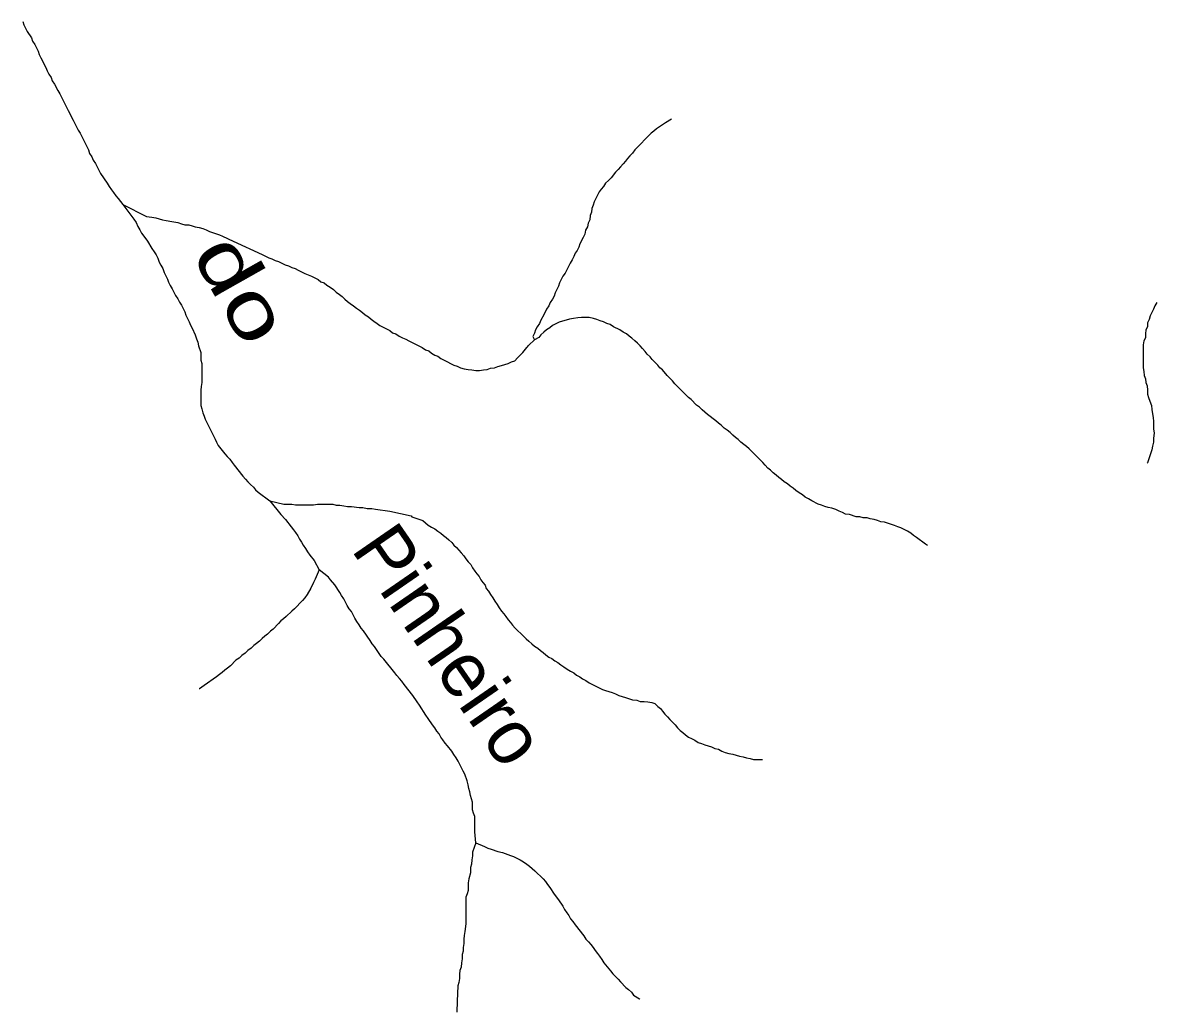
# Model space of a CAD drawing. Extents: x 652.3 to 678, y 7316.9 to 7344.9.
# Drawn here: x 668.578 to 670.225, y 7341.639 to 7343.077 of the extents above; entities that cross this region are included whole.
import ezdxf
from ezdxf.enums import TextEntityAlignment as Align

# ---------------------------------------------------------------- set-up
doc = ezdxf.new("R2010")
doc.units = 0
doc.header["$LTSCALE"] = 0.032
doc.layers.add('61', color=7, linetype='Continuous')
doc.layers.add('7', color=7, linetype='Continuous', lineweight=25)

msp = doc.modelspace()

# ---------------------------------------------------------------- linework, layer by layer
at = {"layer": '7'}
for points in [[(668.5783, 7343.0784), (668.5799, 7343.0737), (668.5823, 7343.0689), (668.5847, 7343.0641), (668.591, 7343.0546), (668.5926, 7343.0498), (668.5958, 7343.045), (668.6006, 7343.0355), (668.6022, 7343.0307), (668.6046, 7343.0259), (668.6117, 7343.0116), (668.6141, 7343.0068), (668.6165, 7343.0021), (668.6197, 7342.9973), (668.6213, 7342.9925), (668.6245, 7342.9877), (668.6292, 7342.9782), (668.6324, 7342.9734), (668.6348, 7342.9686), (668.642, 7342.9543), (668.6443, 7342.9495), (668.6515, 7342.9352), (668.6539, 7342.9304), (668.6587, 7342.9209), (668.6618, 7342.9161), (668.6642, 7342.9113), (668.6714, 7342.897), (668.6738, 7342.8922), (668.6754, 7342.8867), (668.6786, 7342.8819), (668.6809, 7342.8771), (668.6841, 7342.8724), (668.6889, 7342.8628), (668.6913, 7342.858), (668.7008, 7342.8437), (668.704, 7342.8389), (668.7072, 7342.8342), (668.7104, 7342.8302), (668.7136, 7342.8254), (668.7168, 7342.8214), (668.7239, 7342.8127)], [(669.5204, 7342.9368), (669.5116, 7342.9312), (669.5029, 7342.9257), (669.4989, 7342.9225), (669.4949, 7342.9193), (669.491, 7342.9161), (669.4671, 7342.8922), (669.4639, 7342.8875), (669.4599, 7342.8835), (669.4567, 7342.8795), (669.4536, 7342.8755), (669.4504, 7342.8716), (669.4464, 7342.8676), (669.4432, 7342.8636), (669.4392, 7342.8596), (669.4329, 7342.8517), (669.4289, 7342.8477), (669.4249, 7342.8437), (669.4217, 7342.8389), (669.4185, 7342.835), (669.4154, 7342.831), (669.413, 7342.8262), (669.4082, 7342.8167), (669.4066, 7342.8119), (669.405, 7342.8071), (669.4042, 7342.8015), (669.4026, 7342.7968), (669.4018, 7342.7904), (669.3995, 7342.7856), (669.3987, 7342.7801), (669.3955, 7342.7753), (669.3947, 7342.7697), (669.3923, 7342.7649), (669.3875, 7342.7554), (669.3859, 7342.7506), (669.3835, 7342.7458), (669.3804, 7342.7419), (669.3788, 7342.7371), (669.3764, 7342.7323), (669.3732, 7342.7275), (669.3708, 7342.7228), (669.3684, 7342.718), (669.366, 7342.7132), (669.3628, 7342.7084), (669.3605, 7342.7037), (669.3581, 7342.6989), (669.3565, 7342.6941), (669.3517, 7342.6846), (669.3501, 7342.6798), (669.3477, 7342.675), (669.3445, 7342.6703), (669.3422, 7342.6655), (669.339, 7342.6607), (669.335, 7342.6527), (669.331, 7342.6448), (669.3286, 7342.64), (669.3255, 7342.6352), (669.3231, 7342.6305), (669.3215, 7342.6257), (669.3191, 7342.6209), (669.3215, 7342.6161)], [(668.7239, 7342.8127), (668.7239, 7342.8127), (668.7581, 7342.7952)], [(668.7239, 7342.8127), (668.7239, 7342.8127), (668.7398, 7342.7912), (668.7398, 7342.7912)], [(668.7581, 7342.7952), (668.7661, 7342.7944), (668.7717, 7342.7936), (668.7812, 7342.7904), (668.7868, 7342.7896), (668.7947, 7342.788), (668.8035, 7342.7864), (668.8091, 7342.7848), (668.8138, 7342.7832), (668.8194, 7342.7832), (668.8242, 7342.7816), (668.8289, 7342.7801), (668.8345, 7342.7793), (668.8401, 7342.7777), (668.8449, 7342.7761), (668.8496, 7342.7737), (668.864, 7342.7689), (668.8687, 7342.7665), (668.8838, 7342.7594)], [(668.7398, 7342.7912), (668.743, 7342.7864), (668.7454, 7342.7809), (668.7486, 7342.7761), (668.751, 7342.7713), (668.7541, 7342.7665), (668.7597, 7342.7594), (668.7661, 7342.749), (668.7693, 7342.7442), (668.7724, 7342.7395), (668.7748, 7342.7347), (668.7764, 7342.7291), (668.7788, 7342.7244), (668.782, 7342.7196), (668.7836, 7342.714), (668.786, 7342.7092), (668.7884, 7342.7045), (668.79, 7342.6997), (668.7923, 7342.6949), (668.7955, 7342.6901), (668.8003, 7342.6806), (668.8035, 7342.6758), (668.8059, 7342.671), (668.8091, 7342.6663), (668.8138, 7342.6567), (668.8154, 7342.6519), (668.8202, 7342.6424), (668.8218, 7342.6376), (668.8242, 7342.6329), (668.8289, 7342.6233), (668.8305, 7342.6177), (668.8329, 7342.613), (668.8337, 7342.6074), (668.8369, 7342.5978), (668.8369, 7342.5867), (668.8385, 7342.5819), (668.8385, 7342.5541), (668.8377, 7342.5485), (668.8369, 7342.5429), (668.8369, 7342.5207), (668.8385, 7342.5159), (668.8401, 7342.5103), (668.8417, 7342.5055), (668.8433, 7342.5008), (668.848, 7342.4912), (668.8504, 7342.4864), (668.8576, 7342.4721), (668.86, 7342.4673), (668.8624, 7342.4626), (668.8719, 7342.4506), (668.8751, 7342.4467), (668.8791, 7342.4427), (668.8823, 7342.4379), (668.8854, 7342.4339), (668.8982, 7342.418), (668.9021, 7342.414), (668.9053, 7342.4101), (668.9093, 7342.4061), (668.9133, 7342.4021), (668.9165, 7342.3981), (668.9204, 7342.3949), (668.9372, 7342.3822)], [(668.8838, 7342.7594), (668.926, 7342.7403), (668.9356, 7342.7355), (668.9403, 7342.7339), (668.9451, 7342.7315), (668.9499, 7342.7299), (668.9547, 7342.7275), (668.9594, 7342.7252), (668.9642, 7342.7236), (668.969, 7342.7212), (668.9738, 7342.7196), (668.9785, 7342.7172), (668.9833, 7342.7148), (668.9881, 7342.7124), (668.9929, 7342.7108), (668.9976, 7342.7084), (669.0024, 7342.7061), (669.0072, 7342.7037), (669.0112, 7342.7005), (669.0159, 7342.6989), (669.0199, 7342.6957), (669.0247, 7342.6925), (669.0295, 7342.6893), (669.0334, 7342.6854), (669.0382, 7342.6822), (669.0422, 7342.679), (669.0462, 7342.675), (669.0501, 7342.6718), (669.0541, 7342.6687), (669.0589, 7342.6655), (669.0629, 7342.6623), (669.0676, 7342.6591), (669.0716, 7342.6559), (669.0756, 7342.6527), (669.0804, 7342.6496), (669.0844, 7342.6464), (669.0883, 7342.6432), (669.0931, 7342.64), (669.0971, 7342.6368), (669.1019, 7342.6344), (669.1066, 7342.6321), (669.1114, 7342.6297), (669.1154, 7342.6265), (669.1202, 7342.6249), (669.1249, 7342.6217), (669.1297, 7342.6193), (669.1345, 7342.6169), (669.1393, 7342.6146), (669.144, 7342.6122), (669.1488, 7342.6098), (669.1536, 7342.6074), (669.1584, 7342.605), (669.1631, 7342.6018), (669.1679, 7342.6002), (669.1719, 7342.597), (669.1767, 7342.5939), (669.1814, 7342.5923), (669.1854, 7342.5891), (669.1902, 7342.5867), (669.195, 7342.5843), (669.1997, 7342.5819), (669.2045, 7342.5795), (669.2093, 7342.578), (669.2141, 7342.5756), (669.2196, 7342.574), (669.2252, 7342.5732), (669.2308, 7342.5724), (669.2363, 7342.5716), (669.2419, 7342.5716), (669.2475, 7342.5724), (669.253, 7342.5732), (669.2578, 7342.5748), (669.2634, 7342.5756), (669.2682, 7342.5772), (669.2737, 7342.5787), (669.2785, 7342.5803), (669.2833, 7342.5819), (669.2881, 7342.5843), (669.2928, 7342.5859), (669.2968, 7342.5899), (669.3048, 7342.5978), (669.3103, 7342.605), (669.3114, 7342.6062), (669.3125, 7342.6074), (669.3135, 7342.6086), (669.3215, 7342.6161)], [(670.2254, 7342.6703), (670.2222, 7342.6655), (670.2206, 7342.6607), (670.2158, 7342.6512), (670.2142, 7342.6456), (670.2118, 7342.6408), (670.2118, 7342.6352), (670.2095, 7342.6305), (670.2087, 7342.6249), (670.2087, 7342.6193), (670.2063, 7342.6146), (670.2055, 7342.609), (670.2055, 7342.5756), (670.2063, 7342.57), (670.2071, 7342.5644), (670.2087, 7342.5596), (670.2095, 7342.5541), (670.2111, 7342.5493), (670.2118, 7342.5429), (670.2118, 7342.5374), (670.2134, 7342.5326), (670.215, 7342.527), (670.2174, 7342.5207), (670.2182, 7342.5151), (670.219, 7342.5087), (670.2198, 7342.5032), (670.2206, 7342.4976), (670.2206, 7342.4864), (670.2214, 7342.4809), (670.2206, 7342.4729), (670.2206, 7342.4673), (670.219, 7342.4618), (670.2182, 7342.4562), (670.2126, 7342.4403), (670.2116, 7342.4373), (670.2115, 7342.4369)], [(669.3724, 7342.6464), (669.3676, 7342.6448), (669.3621, 7342.6432), (669.3573, 7342.6416), (669.3477, 7342.6368), (669.3438, 7342.6336), (669.339, 7342.6305), (669.335, 7342.6273), (669.331, 7342.6233), (669.3281, 7342.6197), (669.3215, 7342.6161)], [(669.8925, 7342.3173), (669.8922, 7342.3175), (669.8896, 7342.3194), (669.8761, 7342.3289), (669.8721, 7342.3321), (669.8681, 7342.3353), (669.8633, 7342.3384), (669.8538, 7342.3432), (669.849, 7342.3448), (669.8442, 7342.3464), (669.8299, 7342.3512), (669.8243, 7342.352), (669.8196, 7342.3536), (669.8148, 7342.3552), (669.8092, 7342.356), (669.8045, 7342.3575), (669.7989, 7342.3575), (669.7941, 7342.3591), (669.7885, 7342.3591), (669.779, 7342.3623), (669.7734, 7342.3631), (669.7687, 7342.3655), (669.7639, 7342.3671), (669.7591, 7342.3695), (669.7535, 7342.3719), (669.748, 7342.3727), (669.7432, 7342.3743), (669.7384, 7342.3758), (669.7336, 7342.3774), (669.7241, 7342.3822), (669.7193, 7342.3854), (669.7145, 7342.3878), (669.7106, 7342.391), (669.7058, 7342.3941), (669.701, 7342.3973), (669.697, 7342.4005), (669.6931, 7342.4037), (669.6891, 7342.4069), (669.6843, 7342.4101), (669.6803, 7342.4132), (669.6764, 7342.4164), (669.6724, 7342.4196), (669.6684, 7342.4228), (669.6644, 7342.4268), (669.6604, 7342.43), (669.6565, 7342.4339), (669.6533, 7342.4379), (669.6334, 7342.4578), (669.6294, 7342.461), (669.6254, 7342.4642), (669.6214, 7342.4673), (669.6175, 7342.4713), (669.6135, 7342.4745), (669.6095, 7342.4777), (669.6055, 7342.4817), (669.6016, 7342.4849), (669.5968, 7342.488), (669.5928, 7342.492), (669.5888, 7342.4952), (669.5848, 7342.4984), (669.5809, 7342.5016), (669.5769, 7342.5047), (669.5729, 7342.5079), (669.5689, 7342.5111), (669.565, 7342.5143), (669.561, 7342.5183), (669.557, 7342.5215), (669.549, 7342.5294), (669.5451, 7342.5326), (669.5291, 7342.5485), (669.5252, 7342.5525), (669.522, 7342.5565), (669.514, 7342.5644), (669.5077, 7342.5724), (669.5037, 7342.5756), (669.5005, 7342.5795), (669.4925, 7342.5875), (669.4894, 7342.5915), (669.4854, 7342.5955), (669.4822, 7342.5994), (669.4782, 7342.6034), (669.475, 7342.6074), (669.4711, 7342.6114), (669.4671, 7342.6146), (669.4631, 7342.6185), (669.4591, 7342.6217), (669.4551, 7342.6249), (669.4504, 7342.6273), (669.4456, 7342.6305), (669.4361, 7342.6352), (669.4313, 7342.6384), (669.4265, 7342.64), (669.4217, 7342.6424), (669.417, 7342.644), (669.4122, 7342.6456), (669.4074, 7342.6472), (669.401, 7342.6488), (669.3899, 7342.6488), (669.3843, 7342.648), (669.378, 7342.6472), (669.3724, 7342.6464)], [(668.9372, 7342.3822), (668.9578, 7342.3774), (668.969, 7342.3774), (668.9746, 7342.3766), (669.0008, 7342.3766), (669.0064, 7342.3774), (669.0287, 7342.3774), (669.0334, 7342.3758), (669.039, 7342.3758), (669.0446, 7342.375), (669.0501, 7342.3743), (669.0557, 7342.3743), (669.0669, 7342.3727), (669.0724, 7342.3727), (669.0788, 7342.3711), (669.0852, 7342.3711), (669.0907, 7342.3703), (669.1114, 7342.3671)], [(668.9372, 7342.3822), (668.9531, 7342.3623), (668.9602, 7342.3552), (668.9682, 7342.3448), (668.9714, 7342.34), (668.9746, 7342.3361), (668.9777, 7342.3313), (668.9801, 7342.3265), (668.9833, 7342.3225), (668.9857, 7342.3178), (668.9889, 7342.313), (668.9921, 7342.3082), (668.9952, 7342.3034), (669.0016, 7342.2955), (669.0088, 7342.282)], [(669.1114, 7342.3671), (669.1424, 7342.3607), (669.1432, 7342.3591), (669.1592, 7342.3536), (669.1631, 7342.3504), (669.1671, 7342.3472), (669.1719, 7342.344), (669.1767, 7342.3416), (669.1814, 7342.3384), (669.1854, 7342.3353), (669.1894, 7342.3321), (669.1934, 7342.3289), (669.1973, 7342.3257), (669.2013, 7342.3217), (669.2045, 7342.3178), (669.2085, 7342.3146), (669.2117, 7342.3106), (669.2149, 7342.3066), (669.2188, 7342.3026), (669.222, 7342.2979), (669.2252, 7342.2939), (669.2292, 7342.2899), (669.2316, 7342.2851), (669.2347, 7342.2804), (669.2379, 7342.2764), (669.2411, 7342.2724), (669.2435, 7342.2676), (669.2467, 7342.2637), (669.2499, 7342.2597), (669.2515, 7342.2549), (669.2546, 7342.2509), (669.2578, 7342.2461), (669.261, 7342.2414), (669.2642, 7342.2366), (669.2674, 7342.2318), (669.2705, 7342.2271), (669.2737, 7342.2223), (669.2769, 7342.2183), (669.2801, 7342.2143), (669.2833, 7342.2095), (669.2865, 7342.2056), (669.2896, 7342.2016), (669.2936, 7342.1976), (669.2976, 7342.1936), (669.3016, 7342.1897), (669.3056, 7342.1857), (669.3095, 7342.1817), (669.3135, 7342.1785), (669.3175, 7342.1745), (669.3215, 7342.1714), (669.3262, 7342.1682), (669.3302, 7342.165), (669.3342, 7342.1618), (669.3382, 7342.1586), (669.3422, 7342.1554), (669.3469, 7342.1531), (669.3509, 7342.1499), (669.3557, 7342.1475), (669.3597, 7342.1443), (669.3644, 7342.1411), (669.3692, 7342.1379), (669.374, 7342.1348), (669.3788, 7342.1324), (669.3827, 7342.1292), (669.3875, 7342.1268), (669.3915, 7342.1236), (669.3963, 7342.1212), (669.401, 7342.118), (669.4058, 7342.1157), (669.4106, 7342.1133), (669.4154, 7342.1109), (669.4201, 7342.1085), (669.4249, 7342.1069), (669.4297, 7342.1053), (669.4345, 7342.1037), (669.4392, 7342.1021), (669.444, 7342.0997), (669.4488, 7342.0982), (669.4536, 7342.0966), (669.4583, 7342.095), (669.4639, 7342.0934), (669.4703, 7342.0926), (669.475, 7342.091), (669.4806, 7342.091), (669.4862, 7342.0902), (669.4918, 7342.0894), (669.4965, 7342.0878), (669.5005, 7342.0838), (669.5045, 7342.0806), (669.5077, 7342.0767), (669.5108, 7342.0727), (669.5148, 7342.0687), (669.518, 7342.0647), (669.522, 7342.0608), (669.526, 7342.0568), (669.5291, 7342.0528), (669.5331, 7342.0488), (669.5371, 7342.0456), (669.5411, 7342.0425), (669.5451, 7342.0393), (669.5498, 7342.0369)], [(669.0088, 7342.282), (669.0032, 7342.2684), (669.0008, 7342.2637), (668.9968, 7342.2557), (668.9913, 7342.2461), (668.9881, 7342.2414), (668.9849, 7342.2374), (668.973, 7342.2255), (668.969, 7342.2223), (668.961, 7342.2143), (668.957, 7342.2111), (668.9531, 7342.208), (668.9499, 7342.204), (668.9419, 7342.196), (668.938, 7342.1928), (668.934, 7342.1889), (668.93, 7342.1857), (668.926, 7342.1825), (668.922, 7342.1785), (668.9181, 7342.1753), (668.9141, 7342.1721), (668.9101, 7342.1682), (668.9053, 7342.165), (668.9014, 7342.161), (668.8966, 7342.1578), (668.8926, 7342.1538), (668.8878, 7342.1507), (668.8799, 7342.1427), (668.8759, 7342.1395), (668.8719, 7342.1363), (668.8679, 7342.1332), (668.864, 7342.13), (668.86, 7342.1268), (668.8417, 7342.1141), (668.8351, 7342.1095), (668.8348, 7342.1093)], [(669.2363, 7341.8857), (669.2347, 7341.9016), (669.2347, 7341.9239), (669.2332, 7341.9287), (669.2316, 7341.9334), (669.2316, 7341.9446), (669.2284, 7341.9541), (669.2276, 7341.9597), (669.226, 7341.9645), (669.2252, 7341.97), (669.2236, 7341.9756), (669.2204, 7341.9852), (669.218, 7341.9899), (669.2156, 7341.9947), (669.2109, 7342.0043), (669.2077, 7342.009), (669.2045, 7342.0138), (669.2013, 7342.0186), (669.195, 7342.0265), (669.1918, 7342.0305), (669.1886, 7342.0353), (669.1854, 7342.0393), (669.183, 7342.044), (669.1798, 7342.048), (669.1767, 7342.0528), (669.1735, 7342.0568), (669.1671, 7342.0663), (669.1639, 7342.0711), (669.1544, 7342.0854), (669.1512, 7342.0902), (669.1448, 7342.0997), (669.1321, 7342.1157), (669.1289, 7342.1204), (669.1257, 7342.1244), (669.1218, 7342.1284), (669.1186, 7342.1324), (669.1027, 7342.1523), (669.0987, 7342.1562), (669.0891, 7342.1706), (669.086, 7342.1745), (669.0828, 7342.1793), (669.0732, 7342.1936), (669.07, 7342.1976), (669.0669, 7342.2024), (669.0637, 7342.2072), (669.0605, 7342.2119), (669.0557, 7342.2215), (669.0525, 7342.2255), (669.0493, 7342.2302), (669.0446, 7342.2398), (669.0414, 7342.2446), (669.039, 7342.2493), (669.0318, 7342.2605), (669.0255, 7342.2676), (669.0223, 7342.2716), (669.0088, 7342.282)], [(669.5498, 7342.0369), (669.5546, 7342.0345), (669.5594, 7342.0313), (669.5642, 7342.0297), (669.5689, 7342.0281), (669.5737, 7342.0265), (669.5785, 7342.0249), (669.5833, 7342.0226), (669.5888, 7342.0218), (669.5936, 7342.0186), (669.5984, 7342.017), (669.6039, 7342.0154), (669.6095, 7342.0146), (669.6143, 7342.013), (669.6191, 7342.0114), (669.6246, 7342.0106), (669.6294, 7342.009), (669.635, 7342.0082), (669.6397, 7342.0066), (669.6413, 7342.0066), (669.6429, 7342.0066), (669.6445, 7342.0066), (669.6461, 7342.0066), (669.6477, 7342.0066), (669.6493, 7342.0066), (669.6509, 7342.0066), (669.6525, 7342.0066), (669.6529, 7342.0066)], [(669.2363, 7341.8857), (669.2316, 7341.8722), (669.2316, 7341.8666), (669.2308, 7341.861), (669.23, 7341.8547), (669.2284, 7341.8499), (669.2284, 7341.8419), (669.226, 7341.8332), (669.2252, 7341.8276), (669.2252, 7341.8165), (669.2236, 7341.8117), (669.222, 7341.8069), (669.222, 7341.7679), (669.2204, 7341.7568), (669.2196, 7341.7512), (669.2188, 7341.7457), (669.2188, 7341.7393), (669.218, 7341.7337), (669.218, 7341.7282), (669.2164, 7341.7234), (669.2164, 7341.717), (669.2156, 7341.7114), (669.2149, 7341.7051), (669.2133, 7341.7003), (669.2125, 7341.6947), (669.2125, 7341.6884), (669.2117, 7341.6828), (669.2101, 7341.678), (669.2093, 7341.6557), (669.2087, 7341.6398), (669.2087, 7341.6394)], [(669.2363, 7341.8857), (669.2491, 7341.8801), (669.2538, 7341.8777), (669.2586, 7341.8762), (669.2682, 7341.873), (669.2753, 7341.8714), (669.2865, 7341.8674), (669.2912, 7341.8658), (669.3008, 7341.861), (669.3056, 7341.8579), (669.3103, 7341.8547), (669.3143, 7341.8515), (669.3183, 7341.8483), (669.3223, 7341.8451), (669.3342, 7341.8332), (669.3374, 7341.8292), (669.3406, 7341.8252), (669.3438, 7341.8205), (669.3501, 7341.8109), (669.3565, 7341.803), (669.3628, 7341.7934), (669.3652, 7341.7886), (669.3684, 7341.7839), (669.3716, 7341.7799), (669.374, 7341.7751), (669.3772, 7341.7711), (669.3804, 7341.7663), (669.3931, 7341.7504), (669.3963, 7341.7457), (669.4002, 7341.7417), (669.4034, 7341.7377), (669.4066, 7341.7337), (669.4098, 7341.729), (669.413, 7341.725), (669.4162, 7341.721), (669.4193, 7341.7162), (669.4225, 7341.7114), (669.4321, 7341.6995), (669.4353, 7341.6955), (669.4432, 7341.6876), (669.4464, 7341.6836), (669.4544, 7341.6756), (669.4583, 7341.6725), (669.4623, 7341.6685), (669.4655, 7341.6645), (669.4742, 7341.6589), (669.4746, 7341.6587)]]:
    msp.add_lwpolyline(points, dxfattribs=at)

# ---------------------------------------------------------------- texts
at = {"layer": '61', "width": 1.35}
msp.add_text('do', height=0.08, rotation=299.45, dxfattribs=at).set_placement((668.8623, 7342.6706), align=Align.CENTER)
at = {"layer": '61'}
msp.add_text('Pinheiro', height=0.08, rotation=304.623, dxfattribs=at).set_placement((669.1656, 7342.1504), align=Align.CENTER)

doc.saveas('drawing.dxf')
